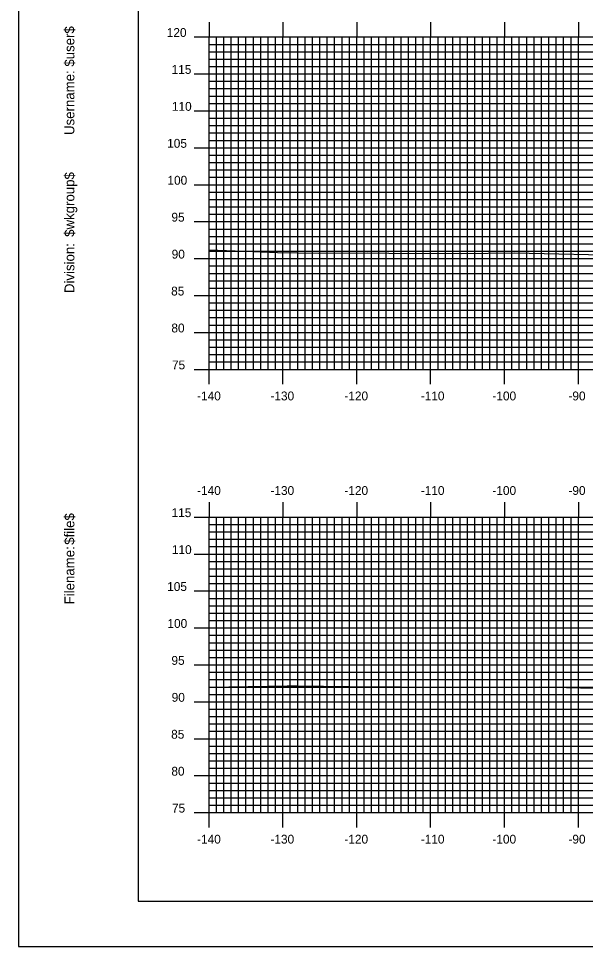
# Model space of a CAD drawing. Extents: x 855297 to 855640, y 364366 to 364586.
# Drawn here: x 855297 to 855373.7, y 364365.7 to 364491.3 of the extents above; entities that cross this region are included whole.
import ezdxf

# ---------------------------------------------------------------- set-up
doc = ezdxf.new("R2010")
doc.units = 0
for name, color, linetype in [('BORDER', 7, 'Continuous'), ('H_V ANNOTATION', 7, 'Continuous'), ('MAJOR', 7, 'Continuous'), ('MINOR', 7, 'Continuous'), ('PLOT BOUNDARY', 7, 'Continuous'), ('S_Roadway_Centerline', 7, 'Continuous')]:
    doc.layers.add(name, color=color, linetype=linetype)

msp = doc.modelspace()

# ---------------------------------------------------------------- linework, layer by layer
at = {"layer": 'BORDER'}
msp.add_lwpolyline([(855313.17, 364371.79), (855633.17, 364371.79), (855633.17, 364581.79), (855313.17, 364581.79)], close=True, dxfattribs=at)
at = {"layer": 'MAJOR'}
for p, q in [((855322.77, 364490.79), (855322.77, 364488.79)), ((855332.77, 364490.79), (855332.77, 364488.79)), ((855342.77, 364490.79), (855342.77, 364488.79)), ((855352.77, 364490.79), (855352.77, 364488.79)), ((855362.77, 364490.79), (855362.77, 364488.79)), ((855372.77, 364490.79), (855372.77, 364488.79)), ((855320.77, 364488.79), (855322.77, 364488.79)), ((855322.77, 364488.79), (855602.77, 364488.79)), ((855322.77, 364443.79), (855322.77, 364488.79)), ((855322.77, 364443.79), (855322.77, 364488.79)), ((855322.77, 364488.79), (855602.77, 364488.79)), ((855332.77, 364443.79), (855332.77, 364488.79)), ((855342.77, 364443.79), (855342.77, 364488.79)), ((855352.77, 364443.79), (855352.77, 364488.79)), ((855362.77, 364443.79), (855362.77, 364488.79)), ((855372.77, 364443.79), (855372.77, 364488.79)), ((855320.77, 364483.79), (855322.77, 364483.79)), ((855322.77, 364483.79), (855602.77, 364483.79)), ((855320.77, 364478.79), (855322.77, 364478.79)), ((855322.77, 364478.79), (855602.77, 364478.79)), ((855320.77, 364473.79), (855322.77, 364473.79)), ((855322.77, 364473.79), (855602.77, 364473.79)), ((855320.77, 364468.79), (855322.77, 364468.79)), ((855322.77, 364468.79), (855602.77, 364468.79)), ((855320.77, 364463.79), (855322.77, 364463.79)), ((855322.77, 364463.79), (855602.77, 364463.79)), ((855320.77, 364458.79), (855322.77, 364458.79)), ((855322.77, 364458.79), (855602.77, 364458.79)), ((855320.77, 364453.79), (855322.77, 364453.79)), ((855322.77, 364453.79), (855602.77, 364453.79)), ((855320.77, 364448.79), (855322.77, 364448.79)), ((855322.77, 364448.79), (855602.77, 364448.79)), ((855320.77, 364443.79), (855322.77, 364443.79)), ((855322.77, 364443.79), (855602.77, 364443.79)), ((855322.77, 364443.79), (855602.77, 364443.79)), ((855322.77, 364441.78), (855322.77, 364443.79)), ((855332.77, 364441.78), (855332.77, 364443.79)), ((855342.77, 364441.78), (855342.77, 364443.79)), ((855352.77, 364441.78), (855352.77, 364443.79)), ((855362.77, 364441.78), (855362.77, 364443.79)), ((855372.77, 364441.78), (855372.77, 364443.79)), ((855322.77, 364425.79), (855322.77, 364423.79)), ((855332.77, 364425.79), (855332.77, 364423.79)), ((855342.77, 364425.79), (855342.77, 364423.79)), ((855352.77, 364425.79), (855352.77, 364423.79)), ((855362.77, 364425.79), (855362.77, 364423.79)), ((855372.77, 364425.79), (855372.77, 364423.79)), ((855320.77, 364423.79), (855322.77, 364423.79)), ((855322.77, 364423.79), (855602.77, 364423.79)), ((855322.77, 364383.79), (855322.77, 364423.79)), ((855322.77, 364383.79), (855322.77, 364423.79)), ((855322.77, 364423.79), (855602.77, 364423.79)), ((855332.77, 364383.79), (855332.77, 364423.79)), ((855342.77, 364383.79), (855342.77, 364423.79)), ((855352.77, 364383.79), (855352.77, 364423.79)), ((855362.77, 364383.79), (855362.77, 364423.79)), ((855372.77, 364383.79), (855372.77, 364423.79)), ((855320.77, 364418.79), (855322.77, 364418.79)), ((855322.77, 364418.79), (855602.77, 364418.79)), ((855320.77, 364413.79), (855322.77, 364413.79)), ((855322.77, 364413.79), (855602.77, 364413.79)), ((855320.77, 364408.79), (855322.77, 364408.79)), ((855322.77, 364408.79), (855602.77, 364408.79)), ((855320.77, 364403.79), (855322.77, 364403.79)), ((855322.77, 364403.79), (855602.77, 364403.79)), ((855320.77, 364398.79), (855322.77, 364398.79)), ((855322.77, 364398.79), (855602.77, 364398.79)), ((855320.77, 364393.79), (855322.77, 364393.79)), ((855322.77, 364393.79), (855602.77, 364393.79)), ((855320.77, 364388.79), (855322.77, 364388.79)), ((855322.77, 364388.79), (855602.77, 364388.79)), ((855320.77, 364383.79), (855322.77, 364383.79)), ((855322.77, 364383.79), (855602.77, 364383.79)), ((855322.77, 364383.79), (855602.77, 364383.79)), ((855322.77, 364381.78), (855322.77, 364383.79)), ((855332.77, 364381.78), (855332.77, 364383.79)), ((855342.77, 364381.78), (855342.77, 364383.79)), ((855352.77, 364381.78), (855352.77, 364383.79)), ((855362.77, 364381.78), (855362.77, 364383.79)), ((855372.77, 364381.78), (855372.77, 364383.79))]:
    msp.add_line(p, q, dxfattribs=at)
at = {"layer": 'MINOR'}
for p, q in [((855322.77, 364487.79), (855602.77, 364487.79)), ((855322.77, 364487.79), (855324.77, 364487.79)), ((855323.77, 364443.79), (855323.77, 364488.79)), ((855324.77, 364443.79), (855324.77, 364488.79)), ((855325.77, 364443.79), (855325.77, 364488.79)), ((855326.77, 364443.79), (855326.77, 364488.79)), ((855327.77, 364443.79), (855327.77, 364488.79)), ((855328.77, 364443.79), (855328.77, 364488.79)), ((855329.77, 364443.79), (855329.77, 364488.79)), ((855330.77, 364443.79), (855330.77, 364488.79)), ((855331.77, 364443.79), (855331.77, 364488.79)), ((855333.77, 364443.79), (855333.77, 364488.79)), ((855334.77, 364443.79), (855334.77, 364488.79)), ((855335.77, 364443.79), (855335.77, 364488.79)), ((855336.77, 364443.79), (855336.77, 364488.79)), ((855337.77, 364443.79), (855337.77, 364488.79)), ((855338.77, 364443.79), (855338.77, 364488.79)), ((855339.77, 364443.79), (855339.77, 364488.79)), ((855340.77, 364443.79), (855340.77, 364488.79)), ((855341.77, 364443.79), (855341.77, 364488.79)), ((855343.77, 364443.79), (855343.77, 364488.79)), ((855344.77, 364443.79), (855344.77, 364488.79)), ((855345.77, 364443.79), (855345.77, 364488.79)), ((855346.77, 364443.79), (855346.77, 364488.79)), ((855347.77, 364443.79), (855347.77, 364488.79)), ((855348.77, 364443.79), (855348.77, 364488.79)), ((855349.77, 364443.79), (855349.77, 364488.79)), ((855350.77, 364443.79), (855350.77, 364488.79)), ((855351.77, 364443.79), (855351.77, 364488.79)), ((855353.77, 364443.79), (855353.77, 364488.79)), ((855354.77, 364443.79), (855354.77, 364488.79)), ((855355.77, 364443.79), (855355.77, 364488.79)), ((855356.77, 364443.79), (855356.77, 364488.79)), ((855357.77, 364443.79), (855357.77, 364488.79)), ((855358.77, 364443.79), (855358.77, 364488.79)), ((855359.77, 364443.79), (855359.77, 364488.79)), ((855360.77, 364443.79), (855360.77, 364488.79)), ((855361.77, 364443.79), (855361.77, 364488.79)), ((855363.77, 364443.79), (855363.77, 364488.79)), ((855364.77, 364443.79), (855364.77, 364488.79)), ((855365.77, 364443.79), (855365.77, 364488.79)), ((855366.77, 364443.79), (855366.77, 364488.79)), ((855367.77, 364443.79), (855367.77, 364488.79)), ((855368.77, 364443.79), (855368.77, 364488.79)), ((855369.77, 364443.79), (855369.77, 364488.79)), ((855370.77, 364443.79), (855370.77, 364488.79)), ((855371.77, 364443.79), (855371.77, 364488.79)), ((855322.77, 364486.79), (855602.77, 364486.79)), ((855322.77, 364486.79), (855324.77, 364486.79)), ((855322.77, 364485.79), (855602.77, 364485.79)), ((855322.77, 364485.79), (855324.77, 364485.79)), ((855322.77, 364484.79), (855602.77, 364484.79)), ((855322.77, 364484.79), (855324.77, 364484.79)), ((855322.77, 364482.79), (855602.77, 364482.79)), ((855322.77, 364482.79), (855324.77, 364482.79)), ((855322.77, 364481.79), (855602.77, 364481.79)), ((855322.77, 364481.79), (855324.77, 364481.79)), ((855322.77, 364480.79), (855602.77, 364480.79)), ((855322.77, 364480.79), (855324.77, 364480.79)), ((855322.77, 364479.79), (855602.77, 364479.79)), ((855322.77, 364479.79), (855324.77, 364479.79)), ((855322.77, 364477.79), (855602.77, 364477.79)), ((855322.77, 364477.79), (855324.77, 364477.79)), ((855322.77, 364476.79), (855602.77, 364476.79)), ((855322.77, 364476.79), (855324.77, 364476.79)), ((855322.77, 364475.79), (855602.77, 364475.79)), ((855322.77, 364475.79), (855324.77, 364475.79)), ((855322.77, 364474.79), (855602.77, 364474.79)), ((855322.77, 364474.79), (855324.77, 364474.79)), ((855322.77, 364472.79), (855602.77, 364472.79)), ((855322.77, 364472.79), (855324.77, 364472.79)), ((855322.77, 364471.79), (855602.77, 364471.79)), ((855322.77, 364471.79), (855324.77, 364471.79)), ((855322.77, 364470.79), (855602.77, 364470.79)), ((855322.77, 364470.79), (855324.77, 364470.79)), ((855322.77, 364469.79), (855602.77, 364469.79)), ((855322.77, 364469.79), (855324.77, 364469.79)), ((855322.77, 364467.79), (855602.77, 364467.79)), ((855322.77, 364467.79), (855324.77, 364467.79)), ((855322.77, 364466.79), (855602.77, 364466.79)), ((855322.77, 364466.79), (855324.77, 364466.79)), ((855322.77, 364465.79), (855602.77, 364465.79)), ((855322.77, 364465.79), (855324.77, 364465.79)), ((855322.77, 364464.79), (855602.77, 364464.79)), ((855322.77, 364464.79), (855324.77, 364464.79)), ((855322.77, 364462.79), (855602.77, 364462.79)), ((855322.77, 364462.79), (855324.77, 364462.79)), ((855322.77, 364461.79), (855602.77, 364461.79)), ((855322.77, 364461.79), (855324.77, 364461.79)), ((855322.77, 364460.79), (855602.77, 364460.79)), ((855322.77, 364460.79), (855324.77, 364460.79)), ((855322.77, 364459.79), (855602.77, 364459.79)), ((855322.77, 364459.79), (855324.77, 364459.79)), ((855322.77, 364457.79), (855602.77, 364457.79)), ((855322.77, 364457.79), (855324.77, 364457.79)), ((855322.77, 364456.79), (855602.77, 364456.79)), ((855322.77, 364456.79), (855324.77, 364456.79)), ((855322.77, 364455.79), (855602.77, 364455.79)), ((855322.77, 364455.79), (855324.77, 364455.79)), ((855322.77, 364454.79), (855602.77, 364454.79)), ((855322.77, 364454.79), (855324.77, 364454.79)), ((855322.77, 364452.79), (855602.77, 364452.79)), ((855322.77, 364452.79), (855324.77, 364452.79)), ((855322.77, 364451.79), (855602.77, 364451.79)), ((855322.77, 364451.79), (855324.77, 364451.79)), ((855322.77, 364450.79), (855602.77, 364450.79)), ((855322.77, 364450.79), (855324.77, 364450.79)), ((855322.77, 364449.79), (855602.77, 364449.79)), ((855322.77, 364449.79), (855324.77, 364449.79)), ((855322.77, 364447.79), (855602.77, 364447.79)), ((855322.77, 364447.79), (855324.77, 364447.79)), ((855322.77, 364446.79), (855602.77, 364446.79)), ((855322.77, 364446.79), (855324.77, 364446.79)), ((855322.77, 364445.79), (855602.77, 364445.79)), ((855322.77, 364445.79), (855324.77, 364445.79)), ((855322.77, 364444.79), (855602.77, 364444.79)), ((855322.77, 364444.79), (855324.77, 364444.79)), ((855323.77, 364383.79), (855323.77, 364423.79)), ((855324.77, 364383.79), (855324.77, 364423.79)), ((855325.77, 364383.79), (855325.77, 364423.79)), ((855326.77, 364383.79), (855326.77, 364423.79)), ((855327.77, 364383.79), (855327.77, 364423.79)), ((855328.77, 364383.79), (855328.77, 364423.79)), ((855329.77, 364383.79), (855329.77, 364423.79)), ((855330.77, 364383.79), (855330.77, 364423.79)), ((855331.77, 364383.79), (855331.77, 364423.79)), ((855333.77, 364383.79), (855333.77, 364423.79)), ((855334.77, 364383.79), (855334.77, 364423.79)), ((855335.77, 364383.79), (855335.77, 364423.79)), ((855336.77, 364383.79), (855336.77, 364423.79)), ((855337.77, 364383.79), (855337.77, 364423.79)), ((855338.77, 364383.79), (855338.77, 364423.79)), ((855339.77, 364383.79), (855339.77, 364423.79)), ((855340.77, 364383.79), (855340.77, 364423.79)), ((855341.77, 364383.79), (855341.77, 364423.79)), ((855343.77, 364383.79), (855343.77, 364423.79)), ((855344.77, 364383.79), (855344.77, 364423.79)), ((855345.77, 364383.79), (855345.77, 364423.79)), ((855346.77, 364383.79), (855346.77, 364423.79)), ((855347.77, 364383.79), (855347.77, 364423.79)), ((855348.77, 364383.79), (855348.77, 364423.79)), ((855349.77, 364383.79), (855349.77, 364423.79)), ((855350.77, 364383.79), (855350.77, 364423.79)), ((855351.77, 364383.79), (855351.77, 364423.79)), ((855353.77, 364383.79), (855353.77, 364423.79)), ((855354.77, 364383.79), (855354.77, 364423.79)), ((855355.77, 364383.79), (855355.77, 364423.79)), ((855356.77, 364383.79), (855356.77, 364423.79)), ((855357.77, 364383.79), (855357.77, 364423.79)), ((855358.77, 364383.79), (855358.77, 364423.79)), ((855359.77, 364383.79), (855359.77, 364423.79)), ((855360.77, 364383.79), (855360.77, 364423.79)), ((855361.77, 364383.79), (855361.77, 364423.79)), ((855363.77, 364383.79), (855363.77, 364423.79)), ((855364.77, 364383.79), (855364.77, 364423.79)), ((855365.77, 364383.79), (855365.77, 364423.79)), ((855366.77, 364383.79), (855366.77, 364423.79)), ((855367.77, 364383.79), (855367.77, 364423.79)), ((855368.77, 364383.79), (855368.77, 364423.79)), ((855369.77, 364383.79), (855369.77, 364423.79)), ((855370.77, 364383.79), (855370.77, 364423.79)), ((855371.77, 364383.79), (855371.77, 364423.79)), ((855322.77, 364422.79), (855602.77, 364422.79)), ((855322.77, 364422.79), (855324.77, 364422.79)), ((855322.77, 364421.79), (855602.77, 364421.79)), ((855322.77, 364421.79), (855324.77, 364421.79)), ((855322.77, 364420.79), (855602.77, 364420.79)), ((855322.77, 364420.79), (855324.77, 364420.79)), ((855322.77, 364419.79), (855602.77, 364419.79)), ((855322.77, 364419.79), (855324.77, 364419.79)), ((855322.77, 364417.79), (855602.77, 364417.79)), ((855322.77, 364417.79), (855324.77, 364417.79)), ((855322.77, 364416.79), (855602.77, 364416.79)), ((855322.77, 364416.79), (855324.77, 364416.79)), ((855322.77, 364415.79), (855602.77, 364415.79)), ((855322.77, 364415.79), (855324.77, 364415.79)), ((855322.77, 364414.79), (855602.77, 364414.79)), ((855322.77, 364414.79), (855324.77, 364414.79)), ((855322.77, 364412.79), (855602.77, 364412.79)), ((855322.77, 364412.79), (855324.77, 364412.79)), ((855322.77, 364411.79), (855602.77, 364411.79)), ((855322.77, 364411.79), (855324.77, 364411.79)), ((855322.77, 364410.79), (855602.77, 364410.79)), ((855322.77, 364410.79), (855324.77, 364410.79)), ((855322.77, 364409.79), (855602.77, 364409.79)), ((855322.77, 364409.79), (855324.77, 364409.79)), ((855322.77, 364407.79), (855602.77, 364407.79)), ((855322.77, 364407.79), (855324.77, 364407.79)), ((855322.77, 364406.79), (855602.77, 364406.79)), ((855322.77, 364406.79), (855324.77, 364406.79)), ((855322.77, 364405.79), (855602.77, 364405.79)), ((855322.77, 364405.79), (855324.77, 364405.79)), ((855322.77, 364404.79), (855602.77, 364404.79)), ((855322.77, 364404.79), (855324.77, 364404.79)), ((855322.77, 364402.79), (855602.77, 364402.79)), ((855322.77, 364402.79), (855324.77, 364402.79)), ((855322.77, 364401.79), (855602.77, 364401.79)), ((855322.77, 364401.79), (855324.77, 364401.79)), ((855322.77, 364400.79), (855602.77, 364400.79)), ((855322.77, 364400.79), (855324.77, 364400.79)), ((855322.77, 364399.79), (855602.77, 364399.79)), ((855322.77, 364399.79), (855324.77, 364399.79)), ((855322.77, 364397.79), (855602.77, 364397.79)), ((855322.77, 364397.79), (855324.77, 364397.79)), ((855322.77, 364396.79), (855602.77, 364396.79)), ((855322.77, 364396.79), (855324.77, 364396.79)), ((855322.77, 364395.79), (855602.77, 364395.79)), ((855322.77, 364395.79), (855324.77, 364395.79)), ((855322.77, 364394.79), (855602.77, 364394.79)), ((855322.77, 364394.79), (855324.77, 364394.79)), ((855322.77, 364392.79), (855602.77, 364392.79)), ((855322.77, 364392.79), (855324.77, 364392.79)), ((855322.77, 364391.79), (855602.77, 364391.79)), ((855322.77, 364391.79), (855324.77, 364391.79)), ((855322.77, 364390.79), (855602.77, 364390.79)), ((855322.77, 364390.79), (855324.77, 364390.79)), ((855322.77, 364389.79), (855602.77, 364389.79)), ((855322.77, 364389.79), (855324.77, 364389.79)), ((855322.77, 364387.79), (855602.77, 364387.79)), ((855322.77, 364387.79), (855324.77, 364387.79)), ((855322.77, 364386.79), (855602.77, 364386.79)), ((855322.77, 364386.79), (855324.77, 364386.79)), ((855322.77, 364385.79), (855602.77, 364385.79)), ((855322.77, 364385.79), (855324.77, 364385.79)), ((855322.77, 364384.79), (855602.77, 364384.79)), ((855322.77, 364384.79), (855324.77, 364384.79))]:
    msp.add_line(p, q, dxfattribs=at)
at = {"layer": 'PLOT BOUNDARY'}
msp.add_lwpolyline([(855296.98, 364365.67), (855636.98, 364365.67), (855636.98, 364585.67), (855296.98, 364585.67)], close=True, dxfattribs=at)
at = {"layer": 'S_Roadway_Centerline'}
for points in [[(855322.77, 364459.99), (855329.86, 364459.7), (855332.04, 364459.61), (855337.52, 364459.53), (855344.27, 364459.55), (855347.12, 364459.51), (855357, 364459.49), (855364.14, 364459.57), (855380.13, 364459.21), (855382.25, 364459.16), (855395.43, 364458.89), (855400.7, 364458.66), (855412.86, 364458.72), (855417.75, 364458.68), (855419.83, 364458.65), (855426.52, 364458.47), (855433.73, 364458.26), (855435.74, 364458.22), (855440.56, 364458.03), (855452.48, 364457.55)], [(855322.77, 364400.75), (855333.36, 364400.94), (855334.68, 364400.95), (855341.84, 364400.88), (855348.82, 364400.81), (855350.16, 364400.79), (855362.89, 364400.79), (855367.46, 364400.82), (855376.76, 364400.58), (855384.77, 364400.28), (855390.32, 364400.13), (855400.94, 364400.04), (855404, 364400.01), (855413.66, 364400.08), (855417.86, 364400.11), (855419.28, 364400.07), (855434.62, 364399.9), (855441.38, 364399.78), (855451.75, 364399.5)]]:
    msp.add_lwpolyline(points, dxfattribs=at)

# ---------------------------------------------------------------- texts
at = {"layer": 'BORDER'}
for s, p in [('$user$', (855304.54, 364484.77)), ('Username:', (855304.54, 364475.52)), ('$wkgroup$', (855304.54, 364461.73)), ('Division:', (855304.54, 364454.12)), ('$file$', (855304.54, 364420.04)), ('Filename:', (855304.54, 364411.98))]:
    msp.add_text(s, height=1.339, rotation=90, dxfattribs=at).set_placement(p)
at = {"layer": 'H_V ANNOTATION'}
for s, p in [('120', (855317.05, 364488.79)), ('115', (855317.7, 364483.79)), ('110', (855317.74, 364478.79)), ('105', (855317.1, 364473.79)), ('100', (855317.14, 364468.79)), ('95', (855317.68, 364463.79)), ('90', (855317.71, 364458.79)), ('85', (855317.64, 364453.79)), ('80', (855317.67, 364448.79)), ('75', (855317.75, 364443.79)), ('-140', (855321.15, 364439.59)), ('-130', (855331.08, 364439.59)), ('-120', (855341.09, 364439.59)), ('-110', (855351.43, 364439.59)), ('-100', (855361.13, 364439.59)), ('-90', (855371.42, 364439.59)), ('-140', (855321.15, 364426.79)), ('-130', (855331.08, 364426.79)), ('-120', (855341.09, 364426.79)), ('-110', (855351.43, 364426.79)), ('-100', (855361.13, 364426.79)), ('-90', (855371.42, 364426.79)), ('115', (855317.7, 364423.79)), ('110', (855317.74, 364418.79)), ('105', (855317.1, 364413.79)), ('100', (855317.14, 364408.79)), ('95', (855317.68, 364403.79)), ('90', (855317.71, 364398.79)), ('85', (855317.64, 364393.79)), ('80', (855317.67, 364388.79)), ('75', (855317.75, 364383.79)), ('-140', (855321.15, 364379.59)), ('-130', (855331.08, 364379.59)), ('-120', (855341.09, 364379.59)), ('-110', (855351.43, 364379.59)), ('-100', (855361.13, 364379.59)), ('-90', (855371.42, 364379.59))]:
    msp.add_text(s, height=1.2, dxfattribs=at).set_placement(p)
at = {"layer": 'MAJOR'}
for p in [(855322.76, 364443.79), (855322.76, 364383.79)]:
    msp.add_text('-', height=0.012, dxfattribs=at).set_placement(p)

doc.saveas('drawing.dxf')
